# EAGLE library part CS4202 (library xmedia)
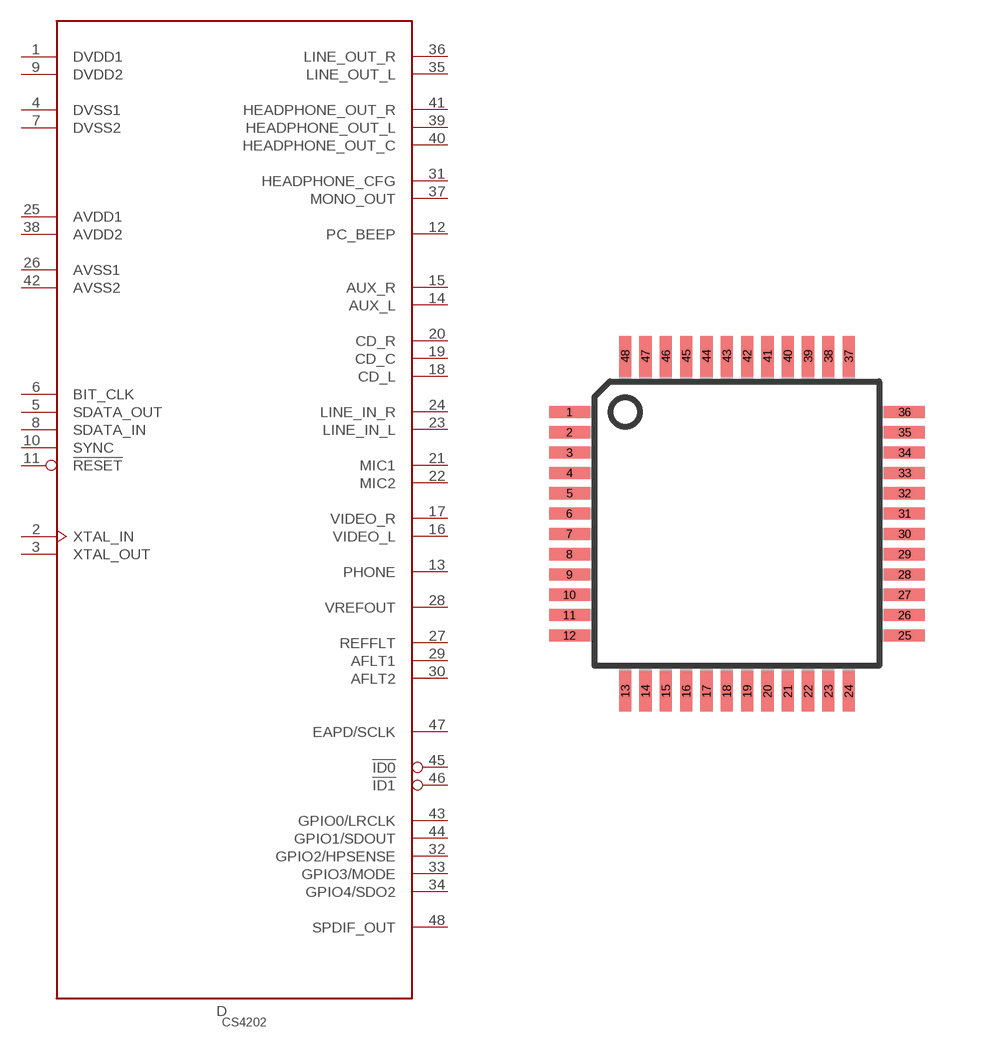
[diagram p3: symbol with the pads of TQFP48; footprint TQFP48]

Designator prefix D

## CS4202  [TQFP48]
1  DVDD1  sup
2  XTAL_IN  in
3  XTAL_OUT  out
4  DVSS1  sup
5  SDATA_OUT  out
6  BIT_CLK  in
7  DVSS2  sup
8  SDATA_IN  in
9  DVDD2  sup
10  SYNC  in
11  !RESET  in
12  PC_BEEP  in
13  PHONE  in
14  AUX_L  in
15  AUX_R  in
16  VIDEO_L  in
17  VIDEO_R  in
18  CD_L  in
19  CD_C  in
20  CD_R  in
21  MIC1  in
22  MIC2  in
23  LINE_IN_L  in
24  LINE_IN_R  in
25  AVDD1  sup
26  AVSS1  sup
27  REFFLT
28  VREFOUT  out
29  AFLT1
30  AFLT2
31  HEADPHONE_CFG  out
32  GPIO2/HPSENSE  out
33  GPIO3/MODE
34  GPIO4/SDO2
35  LINE_OUT_L  out
36  LINE_OUT_R  out
37  MONO_OUT  out
38  AVDD2  sup
39  HEADPHONE_OUT_L  out
40  HEADPHONE_OUT_C  out
41  HEADPHONE_OUT_R  out
42  AVSS2  sup
43  GPIO0/LRCLK
44  GPIO1/SDOUT
45  !ID0
46  !ID1
47  EAPD/SCLK
48  SPDIF_OUT  out

## Footprint TQFP48 (pad centres in mm)
Thin Plasic Quad Flat Package
smd 1.016 x 0.305: 1 -4.191,2.794; 2 -4.191,2.286; 3 -4.191,1.778; 4 -4.191,1.27; 5 -4.191,0.762; 6 -4.191,0.254; 7 -4.191,-0.254; 8 -4.191,-0.762; 9 -4.191,-1.27; 10 -4.191,-1.778; 11 -4.191,-2.286; 12 -4.191,-2.794; 25 4.191,-2.794; 26 4.191,-2.286; 27 4.191,-1.778; 28 4.191,-1.27; 29 4.191,-0.762; 30 4.191,-0.254; 31 4.191,0.254; 32 4.191,0.762; 33 4.191,1.27; 34 4.191,1.778; 35 4.191,2.286; 36 4.191,2.794
smd 0.305 x 1.016: 13 -2.794,-4.191; 14 -2.286,-4.191; 15 -1.778,-4.191; 16 -1.27,-4.191; 17 -0.762,-4.191; 18 -0.254,-4.191; 19 0.254,-4.191; 20 0.762,-4.191; 21 1.27,-4.191; 22 1.778,-4.191; 23 2.286,-4.191; 24 2.794,-4.191; 37 2.794,4.191; 38 2.286,4.191; 39 1.778,4.191; 40 1.27,4.191; 41 0.762,4.191; 42 0.254,4.191; 43 -0.254,4.191; 44 -0.762,4.191; 45 -1.27,4.191; 46 -1.778,4.191; 47 -2.286,4.191; 48 -2.794,4.191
